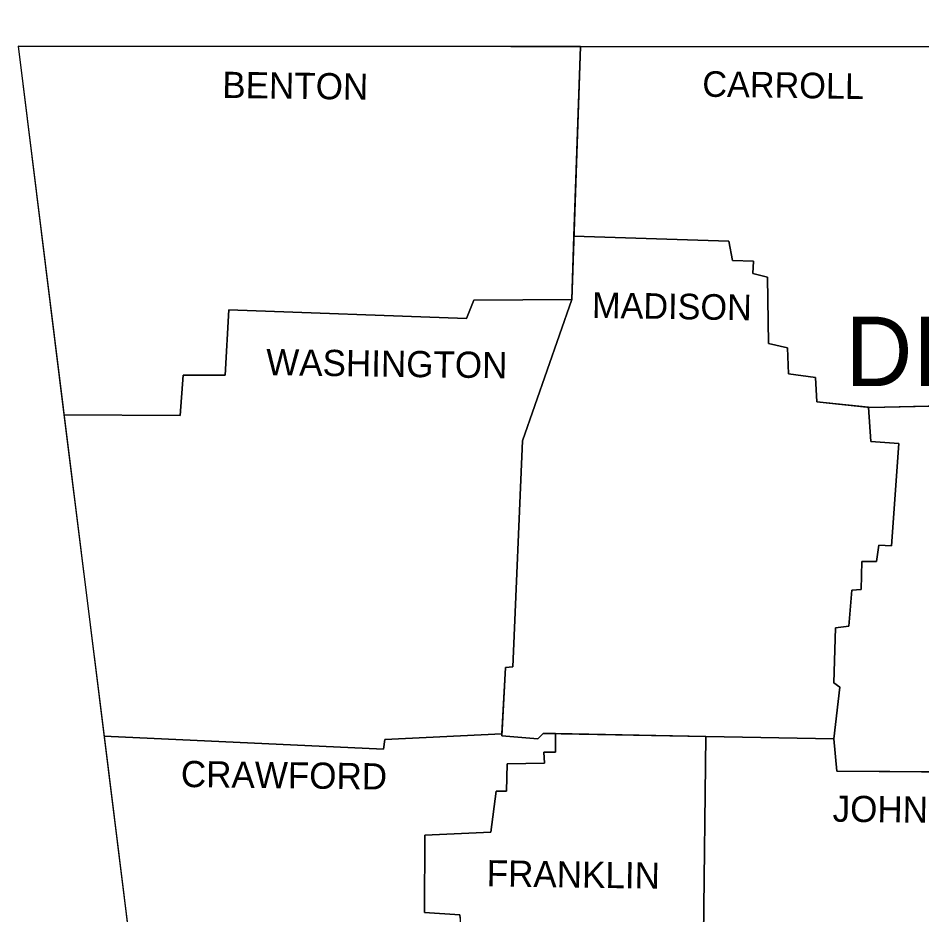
# Model space of a CAD drawing. Extents: x 1370567 to 1373900, y 377514 to 379648.
# Drawn here: x 1373164.5 to 1373319.4, y 379250.1 to 379403.8 of the extents above; entities that cross this region are included whole.
import ezdxf

# ---------------------------------------------------------------- set-up
doc = ezdxf.new("R2010")
doc.units = 0
doc.layers.add('Survey Names', color=7, linetype='Continuous')
doc.layers.add('Survey Symbols', color=7, linetype='Continuous')

msp = doc.modelspace()

# ---------------------------------------------------------------- linework, layer by layer
at = {"layer": 'Survey Names'}
for points in [[(1373164.5, 379398.98), (1373333.34, 379398.88), (1373481.5, 379399.19), (1373656.28, 379401.91), (1373737.31, 379403.79)], [(1373164.5, 379398.98), (1373186.12, 379225.46), (1373176.72, 378942.19)], [(1373260.9, 379398.92), (1373259.41, 379355.55)], [(1373259.79, 379366.44), (1373286.35, 379365.57), (1373286.98, 379362.23), (1373290.53, 379362.13), (1373290.42, 379360.04), (1373292.93, 379359.41), (1373293.14, 379348.03), (1373296.38, 379347.3), (1373296.58, 379342.81), (1373301.18, 379342.19), (1373301.39, 379338.01), (1373310.47, 379337.07), (1373333.86, 379337.59), (1373334.07, 379398.88)], [(1373172.37, 379335.82), (1373192.28, 379335.71), (1373192.8, 379342.6), (1373200, 379342.6), (1373200.63, 379353.78), (1373241.35, 379352.31), (1373242.6, 379355.45), (1373259.41, 379355.55), (1373250.96, 379331.33), (1373249.29, 379292.59), (1373248.03, 379292.49), (1373247.41, 379280.79), (1373253.57, 379280.27), (1373254.51, 379281.21), (1373304.31, 379280.27), (1373304.83, 379274.74)], [(1373310.25, 379337.09), (1373310.68, 379331.22), (1373315.48, 379330.91), (1373314.23, 379313.37), (1373312.04, 379313.47), (1373311.62, 379310.65), (1373309.11, 379310.65), (1373309.01, 379305.85), (1373307.44, 379305.75), (1373306.92, 379299.59), (1373304.62, 379299.27), (1373304.31, 379289.88), (1373305.36, 379289.15), (1373304.31, 379280.27)], [(1373304.83, 379274.74), (1373420.73, 379273.8), (1373421.25, 379284.76), (1373448.46, 379284.44)], [(1373179.24, 379280.71), (1373227.15, 379278.5), (1373227.36, 379280.17), (1373247.42, 379281.12)], [(1373256.6, 379281.17), (1373256.6, 379277.97), (1373254.61, 379277.97), (1373254.72, 379276.09), (1373248.35, 379275.99), (1373248.24, 379271.29), (1373246.47, 379271.29), (1373245.53, 379264.3), (1373234.25, 379263.77), (1373234.15, 379250.51), (1373240.2, 379250.1)], [(1373282.38, 379280.69), (1373281.65, 379220.44)]]:
    msp.add_lwpolyline(points, dxfattribs=at)
at = {"layer": 'Survey Symbols'}
for p, q in [((1373260.9, 379398.92), (1373164.5, 379398.98)), ((1373164.5, 379398.98), (1373172.37, 379335.82)), ((1373260.9, 379398.92), (1373259.79, 379366.44)), ((1373333.34, 379398.88), (1373260.9, 379398.92)), ((1373259.79, 379366.44), (1373259.41, 379355.55)), ((1373286.35, 379365.57), (1373259.79, 379366.44)), ((1373286.98, 379362.23), (1373286.35, 379365.57)), ((1373292.93, 379359.41), (1373290.42, 379360.04)), ((1373293.14, 379348.03), (1373292.93, 379359.41)), ((1373242.6, 379355.45), (1373241.35, 379352.31)), ((1373259.41, 379355.55), (1373242.6, 379355.45)), ((1373200.63, 379353.78), (1373200, 379342.6)), ((1373241.35, 379352.31), (1373200.63, 379353.78)), ((1373296.38, 379347.3), (1373293.14, 379348.03)), ((1373200, 379342.6), (1373192.8, 379342.6)), ((1373310.25, 379337.09), (1373301.39, 379338.01)), ((1373310.47, 379337.07), (1373310.25, 379337.09)), ((1373333.86, 379337.59), (1373310.47, 379337.07)), ((1373172.37, 379335.82), (1373179.24, 379280.71)), ((1373304.62, 379299.27), (1373306.92, 379299.59)), ((1373247.42, 379281.12), (1373248.03, 379292.49)), ((1373248.03, 379292.49), (1373249.29, 379292.59)), ((1373247.41, 379280.79), (1373247.42, 379281.12)), ((1373256.6, 379281.17), (1373254.51, 379281.21)), ((1373256.6, 379281.17), (1373256.6, 379277.97)), ((1373281.65, 379220.44), (1373282.38, 379280.68)), ((1373282.38, 379280.68), (1373281.65, 379220.44)), ((1373282.38, 379280.69), (1373282.38, 379280.68)), ((1373282.38, 379280.68), (1373304.31, 379280.27)), ((1373304.31, 379280.27), (1373282.38, 379280.68)), ((1373304.31, 379280.27), (1373304.83, 379274.74)), ((1373304.83, 379274.74), (1373304.31, 379280.27)), ((1373256.6, 379277.97), (1373254.61, 379277.97)), ((1373254.61, 379277.97), (1373254.72, 379276.09)), ((1373248.35, 379275.99), (1373248.24, 379271.29)), ((1373254.72, 379276.09), (1373248.35, 379275.99)), ((1373304.83, 379274.74), (1373379.48, 379274.13)), ((1373353.52, 379274.34), (1373304.83, 379274.74)), ((1373234.15, 379250.51), (1373240.2, 379250.1))]:
    msp.add_line(p, q, dxfattribs=at)
for points in [[(1373259.41, 379355.55), (1373259.79, 379366.44), (1373260.9, 379398.92)], [(1373259.79, 379366.44), (1373286.35, 379365.57), (1373286.98, 379362.23), (1373290.53, 379362.13), (1373290.42, 379360.04), (1373292.93, 379359.41), (1373293.14, 379348.03), (1373296.38, 379347.3), (1373296.58, 379342.81), (1373301.18, 379342.19), (1373301.39, 379338.01), (1373310.47, 379337.07), (1373333.86, 379337.59), (1373334.07, 379398.88)], [(1373290.42, 379360.04), (1373290.53, 379362.13), (1373286.98, 379362.23)], [(1373172.37, 379335.82), (1373192.28, 379335.71), (1373192.8, 379342.6), (1373200, 379342.6), (1373200.63, 379353.78), (1373241.35, 379352.31), (1373242.6, 379355.45), (1373259.41, 379355.55)], [(1373259.41, 379355.55), (1373250.96, 379331.33), (1373249.29, 379292.59), (1373248.03, 379292.49), (1373247.42, 379281.12), (1373247.41, 379280.79), (1373253.57, 379280.27), (1373254.51, 379281.21), (1373282.38, 379280.68)], [(1373249.29, 379292.59), (1373250.96, 379331.33), (1373259.41, 379355.55)], [(1373301.39, 379338.01), (1373301.18, 379342.19), (1373296.58, 379342.81), (1373296.38, 379347.3)], [(1373192.8, 379342.6), (1373192.28, 379335.71), (1373172.37, 379335.82)], [(1373310.25, 379337.09), (1373310.68, 379331.22), (1373315.48, 379330.91), (1373314.23, 379313.37), (1373312.04, 379313.47), (1373311.62, 379310.65), (1373309.11, 379310.65), (1373309.01, 379305.85), (1373307.44, 379305.75), (1373306.92, 379299.59), (1373304.62, 379299.27), (1373304.31, 379289.88), (1373305.36, 379289.15), (1373304.31, 379280.27)], [(1373314.23, 379313.37), (1373315.48, 379330.91), (1373310.68, 379331.22), (1373310.25, 379337.09)], [(1373311.62, 379310.65), (1373312.04, 379313.47), (1373314.23, 379313.37)], [(1373306.92, 379299.59), (1373307.44, 379305.75), (1373309.01, 379305.85), (1373309.11, 379310.65), (1373311.62, 379310.65)], [(1373304.31, 379280.27), (1373305.36, 379289.15), (1373304.31, 379289.88), (1373304.62, 379299.27)], [(1373179.24, 379280.71), (1373227.15, 379278.5), (1373227.36, 379280.17), (1373247.42, 379281.12)], [(1373247.42, 379281.12), (1373227.36, 379280.17), (1373227.15, 379278.5), (1373179.24, 379280.71)], [(1373179.24, 379280.71), (1373186.12, 379225.46), (1373185.98, 379221.18)], [(1373240.2, 379250.1), (1373234.15, 379250.51), (1373234.25, 379263.77), (1373245.53, 379264.3), (1373246.47, 379271.29), (1373248.24, 379271.29), (1373248.35, 379275.99), (1373254.72, 379276.09), (1373254.61, 379277.97), (1373256.6, 379277.97), (1373256.6, 379281.17)], [(1373254.51, 379281.21), (1373253.57, 379280.27), (1373247.41, 379280.79)], [(1373282.38, 379280.68), (1373282.38, 379280.68), (1373256.6, 379281.17)], [(1373282.38, 379280.68), (1373282.38, 379280.69)], [(1373248.24, 379271.29), (1373246.47, 379271.29), (1373245.53, 379264.3)], [(1373245.53, 379264.3), (1373234.25, 379263.77), (1373234.15, 379250.51)]]:
    msp.add_lwpolyline(points, dxfattribs=at)
for points in [[(1373233.03, 379230.63), (1373233.23, 379230.85), (1373233.42, 379231.09), (1373233.62, 379231.3), (1373234.17, 379231.87), (1373234.75, 379232.4), (1373235.3, 379232.97), (1373235.45, 379233.14), (1373235.6, 379233.3), (1373235.74, 379233.48), (1373235.89, 379233.65), (1373236.02, 379233.83), (1373236.15, 379234.02), (1373236.28, 379234.2), (1373236.4, 379234.39), (1373236.52, 379234.58), (1373236.58, 379234.68), (1373236.64, 379234.78), (1373236.69, 379234.87), (1373236.75, 379234.97), (1373236.81, 379235.06), (1373236.86, 379235.17), (1373236.94, 379235.33), (1373236.99, 379235.5), (1373236.96, 379235.66), (1373236.93, 379235.85), (1373236.9, 379236.03), (1373236.87, 379236.21), (1373236.84, 379236.39), (1373236.8, 379236.58), (1373236.77, 379236.76), (1373236.75, 379236.92), (1373236.78, 379237.09), (1373236.86, 379237.25), (1373236.94, 379237.43), (1373237.04, 379237.56), (1373237.16, 379237.69), (1373237.28, 379237.82), (1373237.4, 379237.96), (1373237.53, 379238.09), (1373237.65, 379238.22), (1373237.77, 379238.35), (1373237.9, 379238.49), (1373238.02, 379238.62), (1373238.12, 379238.77), (1373238.22, 379238.92), (1373238.43, 379239.25), (1373238.61, 379239.59), (1373238.77, 379239.94), (1373238.94, 379240.29), (1373239.07, 379240.64), (1373239.16, 379241.01), (1373239.18, 379241.12), (1373239.19, 379241.23), (1373239.19, 379241.34), (1373239.19, 379241.45), (1373239.19, 379241.56), (1373239.16, 379241.66), (1373239.11, 379241.88), (1373239.06, 379242.1), (1373239.01, 379242.32), (1373238.95, 379242.54), (1373238.9, 379242.76), (1373238.85, 379242.98), (1373238.8, 379243.19), (1373238.8, 379243.41), (1373238.85, 379243.62), (1373238.98, 379244.29), (1373239.15, 379244.96), (1373239.37, 379245.61), (1373239.43, 379245.8), (1373239.5, 379246), (1373239.57, 379246.19), (1373239.64, 379246.38), (1373239.72, 379246.57), (1373239.79, 379246.76), (1373239.87, 379246.95), (1373239.94, 379247.14), (1373240.01, 379247.33), (1373240.08, 379247.52), (1373240.15, 379247.7), (1373240.2, 379247.9), (1373240.3, 379248.26), (1373240.34, 379248.63), (1373240.34, 379248.99), (1373240.33, 379249.18), (1373240.32, 379249.37), (1373240.3, 379249.55), (1373240.27, 379249.73), (1373240.24, 379249.92), (1373240.2, 379250.1)], [(1373240.2, 379250.1), (1373240.24, 379249.92), (1373240.27, 379249.73), (1373240.3, 379249.55), (1373240.3, 379249.5), (1373240.31, 379249.45), (1373240.31, 379249.4)]]:
    msp.add_open_spline(points, degree=3, dxfattribs=at)

# ---------------------------------------------------------------- texts
at = {"layer": 'Survey Names'}
for s, height, rotation, p in [('BENTON', 4.49, 359.2527, (1373199.48, 379390.11)), ('CARROLL', 4.386, 359.1481, (1373281.76, 379390.32)), ('MADISON', 4.386, 359.0906, (1373262.86, 379352.42)), ('WASHINGTON', 4.489, 359.232, (1373207, 379342.6)), ('CRAWFORD', 4.489, 359.2771, (1373192.38, 379272.02)), ('JOHNSON', 4.49, 359.3514, (1373304.1, 379266.07)), ('FRANKLIN', 4.49, 359.1816, (1373244.8, 379255))]:
    msp.add_text(s, height=height, rotation=rotation, dxfattribs=at).set_placement(p)
msp.add_text('DISTRICT 9', height=11.903, dxfattribs=at).set_placement((1373306.3, 379340.72))

doc.saveas('drawing.dxf')
